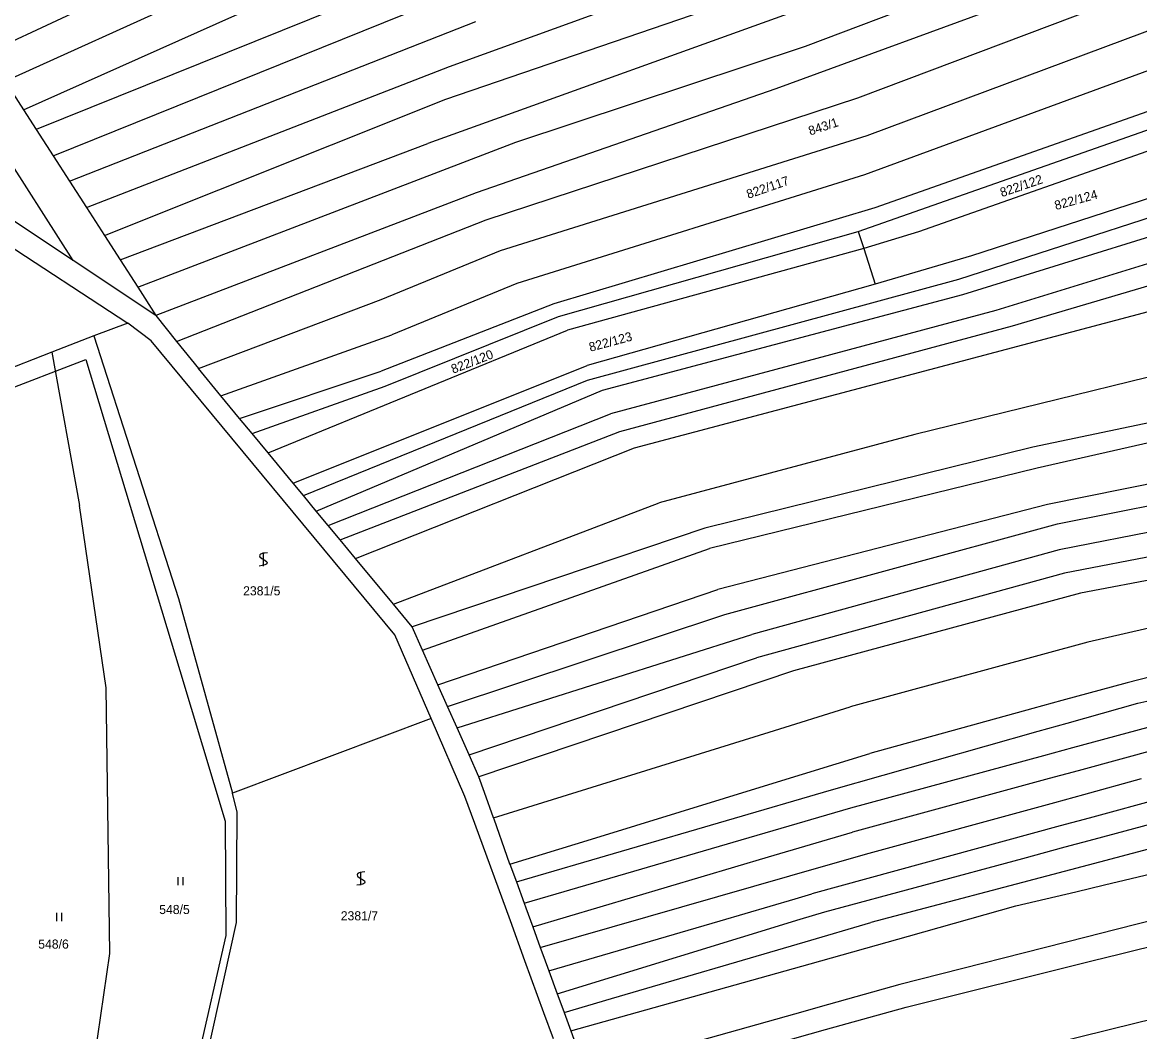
# Model space of a CAD drawing. Extents: x -580630 to -576196, y -1189024 to -1183567.
# Drawn here: x -577503.9 to -577295.7, y -1185459.8 to -1185271.7 of the extents above; entities that cross this region are included whole.
import ezdxf

# ---------------------------------------------------------------- set-up
doc = ezdxf.new("R2010")
doc.units = 0
for name, color, linetype in [('Vrstva 1', 7, 'Continuous'), ('Vrstva 18', 7, 'Continuous'), ('Vrstva 25', 7, 'Continuous'), ('Vrstva 5', 7, 'Continuous'), ('Vrstva 6', 7, 'Continuous')]:
    doc.layers.add(name, color=color, linetype=linetype)

msp = doc.modelspace()

# ---------------------------------------------------------------- linework, layer by layer
at = {"layer": 'Vrstva 1'}
for p, q in [((-577494.43, -1185316.04), (-577543.28, -1185239.79)), ((-577348.23, -1185285.72), (-577291.79, -1185264.43)), ((-577346.48, -1185292.79), (-577290.04, -1185271.7)), ((-577507.16, -1185282.61), (-577503.71, -1185287.97)), ((-577417.52, -1185308.46), (-577348.23, -1185285.72)), ((-577503.71, -1185287.97), (-577501.33, -1185291.67)), ((-577501.33, -1185291.67), (-577498.18, -1185296.57)), ((-577414.84, -1185314.19), (-577346.48, -1185292.79)), ((-577498.18, -1185296.57), (-577495.15, -1185301.28)), ((-577495.15, -1185301.28), (-577491.98, -1185306.2)), ((-577522.29, -1185302.86), (-577484.26, -1185327.73)), ((-577494.43, -1185316.04), (-577511.18, -1185304.95)), ((-577491.98, -1185306.2), (-577488.64, -1185311.39)), ((-577475.19, -1185331.19), (-577417.52, -1185308.46)), ((-577488.64, -1185311.39), (-577485.71, -1185315.94)), ((-577437.05, -1185323.35), (-577414.84, -1185314.19)), ((-577479.03, -1185326.31), (-577494.43, -1185316.04)), ((-577485.71, -1185315.94), (-577482.43, -1185321.03)), ((-577482.43, -1185321.03), (-577479.03, -1185326.31)), ((-577471.12, -1185336.22), (-577437.05, -1185323.35)), ((-577479.03, -1185326.31), (-577475.19, -1185331.19)), ((-577484.26, -1185327.73), (-577490.62, -1185330.08)), ((-577479.95, -1185331.06), (-577484.26, -1185327.73)), ((-577490.62, -1185330.08), (-577498.41, -1185333.13)), ((-577490.62, -1185330.08), (-577474.85, -1185379.08)), ((-577434.5, -1185385.85), (-577479.95, -1185331.06)), ((-577475.19, -1185331.19), (-577471.12, -1185336.22)), ((-577498.41, -1185333.13), (-577508.91, -1185337.25)), ((-577466.92, -1185341.3), (-577471.12, -1185336.22)), ((-577463.44, -1185345.51), (-577466.92, -1185341.3)), ((-577461.13, -1185348.29), (-577463.44, -1185345.51)), ((-577458.14, -1185351.9), (-577461.13, -1185348.29)), ((-577453.46, -1185357.57), (-577458.14, -1185351.9)), ((-577451.54, -1185359.89), (-577453.46, -1185357.57)), ((-577449.16, -1185362.77), (-577451.54, -1185359.89)), ((-577446.93, -1185365.46), (-577449.16, -1185362.77)), ((-577444.69, -1185368.16), (-577446.93, -1185365.46)), ((-577441.85, -1185371.59), (-577444.69, -1185368.16)), ((-577434.79, -1185380.13), (-577441.85, -1185371.59)), ((-577474.85, -1185379.08), (-577464.77, -1185415.33)), ((-577431.3, -1185384.35), (-577434.79, -1185380.13)), ((-577427.72, -1185401.44), (-577434.5, -1185385.85)), ((-577429.35, -1185388.73), (-577431.3, -1185384.35)), ((-577426.48, -1185395.17), (-577429.35, -1185388.73)), ((-577424.68, -1185399.2), (-577426.48, -1185395.17)), ((-577422.92, -1185403.16), (-577424.68, -1185399.2)), ((-577427.72, -1185401.44), (-577464.77, -1185415.33)), ((-577421.45, -1185416), (-577427.72, -1185401.44)), ((-577420.66, -1185408.21), (-577422.92, -1185403.16)), ((-577418.84, -1185412.3), (-577420.66, -1185408.21)), ((-577417.8, -1185415.23), (-577418.84, -1185412.3)), ((-577463.88, -1185418.87), (-577464.77, -1185415.33)), ((-577419.62, -1185421), (-577421.45, -1185416)), ((-577416.12, -1185419.98), (-577417.8, -1185415.23)), ((-577464, -1185439.49), (-577463.88, -1185418.87)), ((-577412.99, -1185439.16), (-577419.62, -1185421)), ((-577416.03, -1185420.23), (-577416.12, -1185419.98)), ((-577413.57, -1185427.16), (-577416.03, -1185420.23)), ((-577413.06, -1185428.6), (-577413.57, -1185427.16)), ((-577413.06, -1185428.6), (-577411.85, -1185431.9)), ((-577411.85, -1185431.9), (-577410.4, -1185435.89)), ((-577410.4, -1185435.89), (-577410.1, -1185436.71)), ((-577410.1, -1185436.71), (-577408.8, -1185440.27)), ((-577474.27, -1185485.61), (-577464, -1185439.49)), ((-577410.27, -1185446.62), (-577412.99, -1185439.16)), ((-577408.8, -1185440.27), (-577407.41, -1185444.1)), ((-577407.41, -1185444.1), (-577406.75, -1185445.9)), ((-577406.75, -1185445.9), (-577405.81, -1185448.48)), ((-577406.73, -1185456.31), (-577410.27, -1185446.62)), ((-577405.81, -1185448.48), (-577404.24, -1185452.79)), ((-577404.24, -1185452.79), (-577403.23, -1185455.57)), ((-577404.97, -1185461.14), (-577406.73, -1185456.31)), ((-577403.23, -1185455.57), (-577402.98, -1185456.25)), ((-577402.98, -1185456.25), (-577401.72, -1185459.69)), ((-577401.72, -1185459.69), (-577399.75, -1185465.11))]:
    msp.add_line(p, q, dxfattribs=at)
at = {"layer": 'Vrstva 25'}
for p, q in [((-577474.94, -1185431.03), (-577474.94, -1185432.53)), ((-577473.94, -1185432.53), (-577473.94, -1185431.03)), ((-577497.58, -1185437.69), (-577497.58, -1185439.19)), ((-577496.58, -1185439.19), (-577496.58, -1185437.69))]:
    msp.add_line(p, q, dxfattribs=at)
for points in [[(-577458.27, -1185370.53), (-577458.78, -1185370.59), (-577459.13, -1185370.64), (-577459.37, -1185370.72), (-577459.55, -1185370.83), (-577459.67, -1185370.92), (-577459.72, -1185371.09), (-577459.67, -1185371.32), (-577459.28, -1185371.64), (-577458.72, -1185371.95), (-577458.37, -1185372.22), (-577458.3, -1185372.42), (-577458.37, -1185372.62), (-577458.53, -1185372.75), (-577458.72, -1185372.82), (-577459.25, -1185372.95), (-577459.77, -1185373.02)], [(-577459.02, -1185373.03), (-577459.02, -1185371.76), (-577459.02, -1185370.53)], [(-577440.08, -1185430.03), (-577440.59, -1185430.09), (-577440.94, -1185430.14), (-577441.18, -1185430.22), (-577441.36, -1185430.33), (-577441.48, -1185430.42), (-577441.53, -1185430.59), (-577441.48, -1185430.82), (-577441.09, -1185431.14), (-577440.53, -1185431.45), (-577440.18, -1185431.72), (-577440.11, -1185431.92), (-577440.18, -1185432.12), (-577440.34, -1185432.25), (-577440.53, -1185432.32), (-577441.06, -1185432.45), (-577441.58, -1185432.52)], [(-577440.83, -1185432.53), (-577440.83, -1185431.26), (-577440.83, -1185430.03)]]:
    msp.add_lwpolyline(points, dxfattribs=at)
at = {"layer": 'Vrstva 5'}
for p, q in [((-577509.43, -1185341.16), (-577492.07, -1185334.55)), ((-577492.07, -1185334.55), (-577474.57, -1185392.51)), ((-577474.57, -1185392.51), (-577466.13, -1185420.58)), ((-577466.13, -1185420.58), (-577465.99, -1185441.92)), ((-577465.99, -1185441.92), (-577478.26, -1185495.26))]:
    msp.add_line(p, q, dxfattribs=at)
at = {"layer": 'Vrstva 6'}
for p, q in [((-577424.36, -1185279.88), (-577280.77, -1185227.94)), ((-577279.63, -1185240.65), (-577428.39, -1185294.25)), ((-577266.81, -1185248.6), (-577363.54, -1185284.08)), ((-577510.51, -1185277.4), (-577449.52, -1185248.83)), ((-577507.16, -1185282.61), (-577446.22, -1185254.93)), ((-577357.98, -1185276.13), (-577306.69, -1185256.67)), ((-577419.87, -1185258.8), (-577501.33, -1185291.67)), ((-577503.71, -1185287.97), (-577444.8, -1185261.65)), ((-577425.01, -1185286), (-577356.86, -1185262.65)), ((-577498.18, -1185296.57), (-577421.97, -1185265.77)), ((-577495.15, -1185301.28), (-577419.42, -1185271.54)), ((-577252.59, -1185273.62), (-577345.1, -1185306.23)), ((-577411.95, -1185294.03), (-577357.98, -1185276.13)), ((-577287.88, -1185278.39), (-577347, -1185300.09)), ((-577491.98, -1185306.2), (-577424.36, -1185279.88)), ((-577488.64, -1185311.39), (-577425.01, -1185286)), ((-577363.54, -1185284.08), (-577419.35, -1185303.43)), ((-577348.19, -1185310.63), (-577274.95, -1185284.92)), ((-577273.68, -1185288.46), (-577336.94, -1185310.73)), ((-577329.44, -1185319.52), (-577244.93, -1185292.25)), ((-577485.71, -1185315.94), (-577428.39, -1185294.25)), ((-577482.43, -1185321.03), (-577411.95, -1185294.03)), ((-577328.69, -1185322.43), (-577244.19, -1185296.2)), ((-577319.42, -1185328.27), (-577211.78, -1185296.39)), ((-577270.67, -1185296.86), (-577327.07, -1185315.2)), ((-577347, -1185300.09), (-577411.76, -1185320.36)), ((-577244.27, -1185301.24), (-577322.5, -1185325.41)), ((-577419.35, -1185303.43), (-577479.03, -1185326.31)), ((-577345.1, -1185306.23), (-577404.87, -1185324.16)), ((-577404.01, -1185326.51), (-577348.19, -1185310.63)), ((-577348.19, -1185310.63), (-577347.1, -1185313.8)), ((-577336.94, -1185310.73), (-577347.1, -1185313.8)), ((-577347.1, -1185313.8), (-577402.32, -1185329.04)), ((-577347.1, -1185313.8), (-577345.04, -1185320.49)), ((-577327.07, -1185315.2), (-577345.04, -1185320.49)), ((-577411.76, -1185320.36), (-577435.1, -1185329.93)), ((-577345.04, -1185320.49), (-577398.69, -1185335.65)), ((-577398.62, -1185338.35), (-577329.44, -1185319.52)), ((-577395.82, -1185340.23), (-577328.69, -1185322.43)), ((-577404.87, -1185324.16), (-577437.05, -1185336.71)), ((-577322.5, -1185325.41), (-577394.32, -1185344.66)), ((-577389.83, -1185350.96), (-577289.08, -1185324.21)), ((-577436.34, -1185339.47), (-577404.01, -1185326.51)), ((-577458.14, -1185351.9), (-577402.32, -1185329.04)), ((-577392.62, -1185347.92), (-577319.42, -1185328.27)), ((-577199.75, -1185328.66), (-577314.8, -1185354.79)), ((-577466.92, -1185341.3), (-577435.1, -1185329.93)), ((-577498.41, -1185333.13), (-577493.26, -1185361.76)), ((-577275.79, -1185333.3), (-577337.63, -1185348.5)), ((-577453.46, -1185357.57), (-577398.69, -1185335.65)), ((-577463.44, -1185345.51), (-577437.05, -1185336.71)), ((-577461.13, -1185348.29), (-577436.34, -1185339.47)), ((-577451.54, -1185359.89), (-577398.62, -1185338.35)), ((-577449.16, -1185362.77), (-577395.82, -1185340.23)), ((-577280.39, -1185343.46), (-577315.66, -1185350.86)), ((-577446.93, -1185365.46), (-577394.32, -1185344.66)), ((-577444.69, -1185368.16), (-577392.62, -1185347.92)), ((-577337.63, -1185348.5), (-577385.29, -1185361.25)), ((-577311.03, -1185365.13), (-577224.16, -1185347.95)), ((-577441.85, -1185371.59), (-577389.83, -1185350.96)), ((-577315.66, -1185350.86), (-577376.73, -1185365.99)), ((-577271.75, -1185353.3), (-577312.87, -1185361.53)), ((-577222.84, -1185352.74), (-577310.75, -1185370.02)), ((-577314.8, -1185354.79), (-577375.87, -1185369.76)), ((-577222.45, -1185357.51), (-577309.73, -1185374.37)), ((-577488.34, -1185395.73), (-577493.26, -1185361.76)), ((-577434.79, -1185380.13), (-577385.29, -1185361.25)), ((-577312.87, -1185361.53), (-577374.35, -1185377.37)), ((-577223.17, -1185362.12), (-577306.75, -1185378.07)), ((-577373, -1185382.05), (-577311.03, -1185365.13)), ((-577376.73, -1185365.99), (-577431.3, -1185384.35)), ((-577429.35, -1185388.73), (-577375.87, -1185369.76)), ((-577310.75, -1185370.02), (-577368.02, -1185385.76)), ((-577309.73, -1185374.37), (-577367.1, -1185390.11)), ((-577426.48, -1185395.17), (-577374.35, -1185377.37)), ((-577261.93, -1185377.12), (-577305.37, -1185387.23)), ((-577306.75, -1185378.07), (-577360.21, -1185392.57)), ((-577424.68, -1185399.2), (-577373, -1185382.05)), ((-577422.92, -1185403.16), (-577368.02, -1185385.76)), ((-577305.37, -1185387.23), (-577349.68, -1185399.26)), ((-577420.66, -1185408.21), (-577367.1, -1185390.11)), ((-577296.08, -1185398.58), (-577255.6, -1185389.62)), ((-577287.67, -1185392.14), (-577298.07, -1185394.78)), ((-577360.21, -1185392.57), (-577418.84, -1185412.3)), ((-577487.62, -1185445.23), (-577488.34, -1185395.73)), ((-577298.07, -1185394.78), (-577310.2, -1185398.11)), ((-577310.2, -1185398.11), (-577315.62, -1185399.6)), ((-577364.74, -1185403.96), (-577349.68, -1185399.26)), ((-577315.62, -1185399.6), (-577346.01, -1185407.95)), ((-577309.25, -1185402.31), (-577296.08, -1185398.58)), ((-577314.62, -1185403.83), (-577309.25, -1185402.31)), ((-577416.12, -1185419.98), (-577364.74, -1185403.96)), ((-577353.15, -1185414.74), (-577314.62, -1185403.83)), ((-577308.18, -1185406.86), (-577294.16, -1185403.06)), ((-577364.81, -1185413.74), (-577346.01, -1185407.95)), ((-577349.57, -1185418.08), (-577313.57, -1185408.32)), ((-577313.57, -1185408.32), (-577308.18, -1185406.86)), ((-577291.99, -1185407.06), (-577307.17, -1185411.18)), ((-577312.56, -1185412.64), (-577349.26, -1185422.6)), ((-577307.17, -1185411.18), (-577312.56, -1185412.64)), ((-577306.15, -1185415.6), (-577295.35, -1185412.65)), ((-577411.85, -1185431.9), (-577353.15, -1185414.74)), ((-577397.9, -1185423.93), (-577364.81, -1185413.74)), ((-577346.82, -1185426.71), (-577311.53, -1185417.07)), ((-577311.53, -1185417.07), (-577306.15, -1185415.6)), ((-577289.9, -1185415.82), (-577305.15, -1185419.99)), ((-577410.4, -1185435.89), (-577349.57, -1185418.08)), ((-577302.26, -1185432.44), (-577241.04, -1185417.86)), ((-577305.15, -1185419.99), (-577310.52, -1185421.46)), ((-577304.22, -1185423.94), (-577288.71, -1185419.76)), ((-577364.87, -1185427.23), (-577349.26, -1185422.6)), ((-577310.52, -1185421.46), (-577356.84, -1185434.13)), ((-577413.06, -1185428.6), (-577397.9, -1185423.93)), ((-577317.5, -1185427.52), (-577309.6, -1185425.39)), ((-577309.6, -1185425.39), (-577304.22, -1185423.94)), ((-577286.57, -1185423.82), (-577303.23, -1185428.22)), ((-577408.8, -1185440.27), (-577364.87, -1185427.23)), ((-577360.89, -1185430.75), (-577346.82, -1185426.71)), ((-577354.42, -1185437.46), (-577317.5, -1185427.52)), ((-577308.61, -1185429.64), (-577345.79, -1185439.46)), ((-577303.23, -1185428.22), (-577308.61, -1185429.64)), ((-577407.41, -1185444.1), (-577360.89, -1185430.75)), ((-577318.77, -1185436.37), (-577307.64, -1185433.72)), ((-577307.64, -1185433.72), (-577302.26, -1185432.44)), ((-577373.92, -1185439.13), (-577359.9, -1185435.03)), ((-577359.9, -1185435.03), (-577356.84, -1185434.13)), ((-577359.01, -1185438.87), (-577354.42, -1185437.46)), ((-577338.79, -1185442), (-577318.77, -1185436.37)), ((-577282.31, -1185436.21), (-577300.34, -1185440.81)), ((-577405.81, -1185448.48), (-577373.92, -1185439.13)), ((-577404.24, -1185452.79), (-577359.01, -1185438.87)), ((-577358.05, -1185443.06), (-577345.79, -1185439.46)), ((-577357.11, -1185447.15), (-577338.79, -1185442)), ((-577305.67, -1185442.17), (-577340.4, -1185451.03)), ((-577300.34, -1185440.81), (-577305.67, -1185442.17)), ((-577299.31, -1185445.31), (-577282.12, -1185441.04)), ((-577394.16, -1185453.66), (-577358.05, -1185443.06)), ((-577503.56, -1185553.76), (-577487.62, -1185445.23)), ((-577304.62, -1185446.63), (-577299.31, -1185445.31)), ((-577401.72, -1185459.69), (-577357.11, -1185447.15)), ((-577339.26, -1185455.24), (-577304.62, -1185446.63)), ((-577340.4, -1185451.03), (-577355.26, -1185455.19)), ((-577402.98, -1185456.25), (-577394.16, -1185453.66)), ((-577296.35, -1185458.15), (-577281.93, -1185454.59)), ((-577358.03, -1185455.97), (-577398.9, -1185467.44)), ((-577355.26, -1185455.19), (-577358.03, -1185455.97)), ((-577354.28, -1185459.44), (-577339.26, -1185455.24)), ((-577301.63, -1185459.45), (-577296.35, -1185458.15)), ((-577397.41, -1185471.49), (-577354.28, -1185459.44)), ((-577340.7, -1185469.09), (-577301.63, -1185459.45))]:
    msp.add_line(p, q, dxfattribs=at)

# ---------------------------------------------------------------- texts
at = {"layer": 'Vrstva 18'}
for s, rotation, p in [('843/1', 18.27735, (-577357.118, -1185292.773)), ('822/117', 19.19409, (-577368.643, -1185304.577)), ('822/122', 18.85031, (-577321.398, -1185304.266)), ('822/124', 15.52716, (-577311.329, -1185306.671)), ('822/123', 15.01149, (-577398.085, -1185333.083)), ('822/120', 21.31403, (-577423.644, -1185337.192))]:
    msp.add_text(s, height=1.7, rotation=rotation, dxfattribs=at).set_placement(p)
for s, p in [('2381/5', (-577462.789, -1185378.49)), ('548/5', (-577478.424, -1185437.89)), ('2381/7', (-577444.592, -1185439.07)), ('548/6', (-577500.967, -1185444.34))]:
    msp.add_text(s, height=1.7, dxfattribs=at).set_placement(p)

doc.saveas('drawing.dxf')
